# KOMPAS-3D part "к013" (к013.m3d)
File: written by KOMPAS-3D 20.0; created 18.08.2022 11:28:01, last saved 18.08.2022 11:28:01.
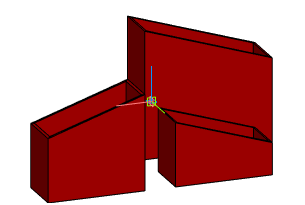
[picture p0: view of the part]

Document properties: Автор: artemsv220@gmail.com; Полное имя файла: \\192.168.2.25\новая общая папка\Медиа\Светильники\Кашпо\Кашпо и вазоны\DWG\к013.m3d

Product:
- Part/product: к013

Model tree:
1. Операция без истории:1
2. Операция без истории:2
3. Операция без истории:3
